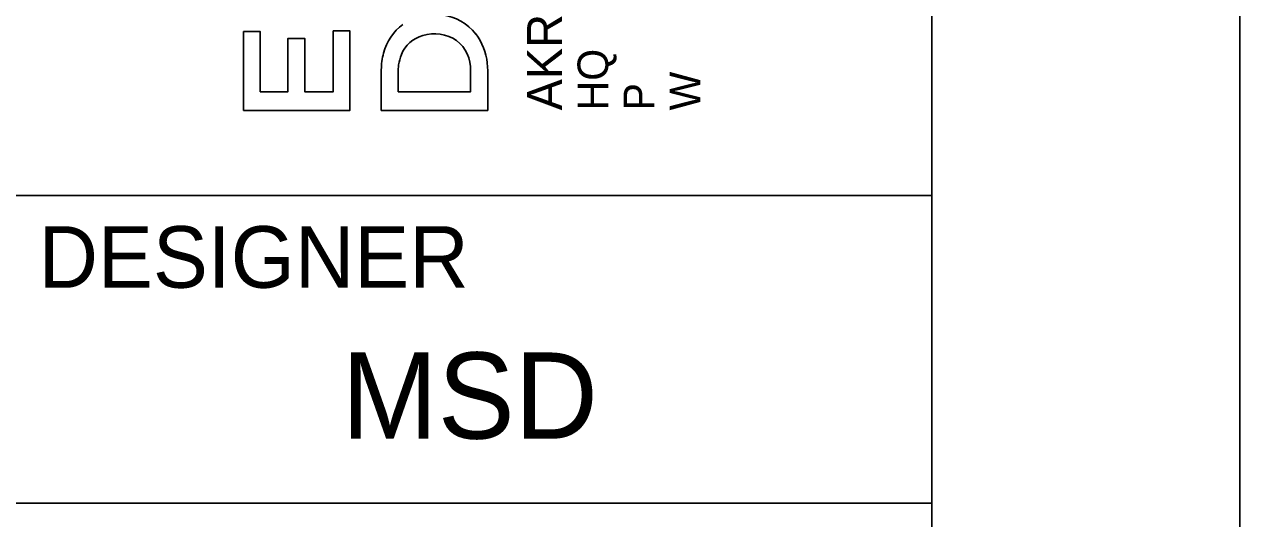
# Model space of a CAD drawing. Extents: x -1 to 34, y 0 to 22.
# Drawn here: x 32.027 to 34, y 2.475 to 3.278 of the extents above; entities that cross this region are included whole.
import ezdxf

# ---------------------------------------------------------------- set-up
doc = ezdxf.new("R2010")
doc.units = 0
for name, color, linetype in [('SH_Border', 7, 'Continuous'), ('SH_Cut_Line', 7, 'Continuous'), ('SH_Data', 7, 'Continuous')]:
    doc.layers.add(name, color=color, linetype=linetype)

msp = doc.modelspace()

# ---------------------------------------------------------------- linework, layer by layer
at = {"layer": 'SH_Border'}
for p, q in [((32, 3), (33.5, 3)), ((32, 2.5), (33.5, 2.5))]:
    msp.add_line(p, q, dxfattribs=at)
msp.add_lwpolyline([(1.5, 21.5), (33.5, 21.5), (33.5, 0.5), (1.5, 0.5)], close=True, dxfattribs=at)
at = {"layer": 'SH_Cut_Line'}
msp.add_lwpolyline([(0, 0), (34, 0), (34, 22), (0, 22)], close=True, dxfattribs=at)
at = {"layer": 'SH_Data'}
for p, q in [((32.383, 3.1379), (32.383, 3.266)), ((32.383, 3.266), (32.4101, 3.266)), ((32.4101, 3.266), (32.4101, 3.1683)), ((32.5286, 3.1683), (32.5286, 3.2672)), ((32.5286, 3.2672), (32.5557, 3.2672)), ((32.5557, 3.2672), (32.5557, 3.1379)), ((32.455, 3.1683), (32.455, 3.2549)), ((32.455, 3.2549), (32.4822, 3.2549)), ((32.4822, 3.2549), (32.4822, 3.1683)), ((32.6064, 3.138), (32.6064, 3.204)), ((32.6347, 3.2118), (32.6341, 3.2023)), ((32.6341, 3.2023), (32.6341, 3.1684)), ((32.7515, 3.1683), (32.7515, 3.2024)), ((32.7785, 3.215), (32.7792, 3.2021)), ((32.7792, 3.2021), (32.7792, 3.138)), ((32.4101, 3.1683), (32.455, 3.1683)), ((32.4822, 3.1683), (32.5286, 3.1683)), ((32.6341, 3.1684), (32.7515, 3.1683)), ((32.5557, 3.1379), (32.383, 3.1379)), ((32.7792, 3.138), (32.6064, 3.138))]:
    msp.add_line(p, q, dxfattribs=at)
msp.add_lwpolyline([(32.383, 3.1379), (32.383, 3.266), (32.4101, 3.266), (32.4101, 3.1683), (32.455, 3.1683), (32.455, 3.2549), (32.4822, 3.2549), (32.4822, 3.1683), (32.5286, 3.1683), (32.5286, 3.2672), (32.5557, 3.2672), (32.5557, 3.1379)], close=True, dxfattribs=at)
for points in [[(32.7785, 3.215), (32.7792, 3.2021), (32.7792, 3.138), (32.6064, 3.138)], [(32.6064, 3.138), (32.6064, 3.204)], [(32.6347, 3.2118), (32.6341, 3.2023), (32.6341, 3.1684), (32.7515, 3.1683), (32.7515, 3.2024)]]:
    msp.add_lwpolyline(points, dxfattribs=at)
for centre, radius, start, end in [((32.6939, 3.2089), 0.0865, 127.2362, 165.148), ((32.6939, 3.2089), 0.0865, 127.2362, 165.148), ((32.6946, 3.2113), 0.0827, 37.8521, 82.402), ((32.6946, 3.2113), 0.0827, 37.8521, 82.402), ((32.6889, 3.2078), 0.054, 106.1881, 157.3861), ((32.6889, 3.2078), 0.054, 106.1881, 157.3861), ((32.6928, 3.1986), 0.0639, 55.6727, 107.2093), ((32.6928, 3.1986), 0.0639, 55.6727, 107.2093), ((32.6859, 3.2057), 0.0931, 5.7333, 37.304), ((32.6859, 3.2057), 0.0931, 5.7333, 37.304), ((32.6929, 3.205), 0.0587, 357.4662, 52.2665), ((32.6929, 3.205), 0.0587, 357.4662, 52.2665), ((32.7143, 3.2028), 0.1078, 164.7861, 179.3704), ((32.7143, 3.2028), 0.1078, 164.7861, 179.3704), ((32.6983, 3.2039), 0.0641, 157.3571, 172.9275), ((32.6983, 3.2039), 0.0641, 157.3571, 172.9275)]:
    msp.add_arc(centre, radius, start, end, dxfattribs=at)

# ---------------------------------------------------------------- texts
for s, height, p in [('AKRON / CLEVELAND / COLUMBUS', 0.056969, (32.9001, 3.138)), ('HQ ', 0.04985, (32.9749, 3.138)), ('W', 0.0498, (33.1244, 3.138)), ('P', 0.0498, (33.0497, 3.138))]:
    msp.add_text(s, height=height, rotation=90, dxfattribs=at).set_placement(p)
for s, height, p in [('DESIGNER', 0.1, (32.05, 2.85)), ('MSD', 0.14, (32.5422, 2.605))]:
    msp.add_text(s, height=height, dxfattribs=at).set_placement(p)

doc.saveas('drawing.dxf')
